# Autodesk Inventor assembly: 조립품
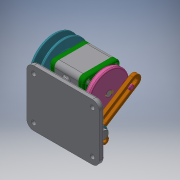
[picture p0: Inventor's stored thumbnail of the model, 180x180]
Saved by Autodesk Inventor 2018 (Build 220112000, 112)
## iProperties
Created: 2020-11
Part Number: 조립품
Document SubType Name: Assembly
Designer: Administrator
Mass: 1532.4 g
Surface Area: 1486.39 cm^2
Volume: 469.454 cm^3
Density: 3.26422 g/cm^3
Author: Administrator
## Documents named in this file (19)
- C:\Users\Administrator\Desktop\601106V1052\조립품.iam
- C:\Users\Administrator\Desktop\601106V1052\본체.ipt
- C:\Users\Administrator\Desktop\601106V1052\축.ipt
- C:\Users\Administrator\Desktop\601106V1052\베어링 6004.ipt
- C:\Users\Administrator\Desktop\601106V1052\커버.ipt
- C:\Users\Administrator\Desktop\601106V1052\오일 실 17 30 5.ipt
- C:\Users\Administrator\Desktop\601106V1052\키 4 x 4 x 8.ipt
- C:\Users\Administrator\Desktop\601106V1052\키 5 x 5 x 12.ipt
- C:\Users\Administrator\Desktop\601106V1052\V-벨트풀리.ipt
- C:\Users\Administrator\Desktop\601106V1052\너트 M10x1.ipt
- C:\Users\Administrator\Desktop\601106V1052\힌지.ipt
- C:\Users\Administrator\Desktop\601106V1052\크랭크.ipt
- C:\Users\Administrator\Desktop\601106V1052\돌림판.ipt
- C:\Users\Administrator\Desktop\601106V1052\힌지 축.ipt
- C:\Users\Administrator\Desktop\601106V1052\볼트 M4.ipt
- C:\Users\Administrator\Desktop\601106V1052\핀 3 x 8.ipt
- C:\Users\Administrator\Desktop\601106V1052\멈춤나사 M3x5.ipt
- C:\Users\Administrator\Desktop\601106V1052\와셔 8x15.5.ipt
- C:\Users\Administrator\Desktop\601106V1052\너트 M8.ipt
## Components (3 placed, 2 different names)
1. V-벨트풀리:1
2. 핀 3 x 8:1 — 플러쉬:3
3. 핀 3 x 8:2 — 플러쉬:2
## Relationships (2: Flush 2)
- 플러쉬:2 [Flush]: 핀 3 x 8:2
- 플러쉬:3 [Flush]: 핀 3 x 8:1
